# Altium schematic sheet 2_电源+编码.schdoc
size 431 x 309 mm; Symbol: Sheet-Symbol_A3; Device: Sheet-Symbol_A3; Company: 嘉立创EDA; Version: V1.0; Page Size: A3; @Project Name: 电容触摸键盘-第一验证板; @Page Count: 2; @Update Date: 2024-10-14; @Create Date: 2024-10-14; @Schematic Name: Schematic1; @Page No: 2; @Page Name: 电源+编码; Title Block Position: 3; Width: 1170; Height: 825; Region Start: 1; X Region Count: 6; Y Region Count: 4; Blade Width: 10; @Board Name: Board1; @Create Time: 23:12:04; @Update Time: 23:19:14
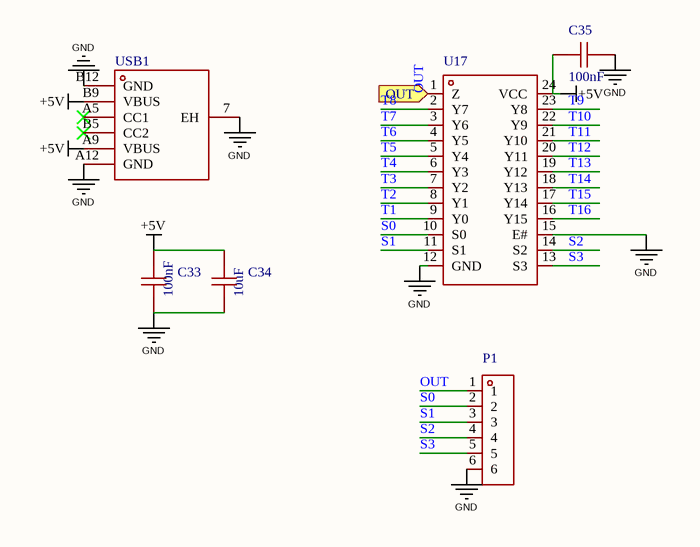
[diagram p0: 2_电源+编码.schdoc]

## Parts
C33  100nF  [C0603]
C34  10uF  [C0603]
C35  100nF  [C0603]
P1  2.54-1*6P母  [hdr-th_6p-p2.54-v-f]  (value not drawn)
U17  74HC4067PW/C2118  [TSSOP-24_L7.8-W4.4-P0.65-LS6.4-BL]  (value not drawn)
USB1  TYPE-C 6P  [TYPE-C-SMD_TYPE-C-6P]  (value not drawn)

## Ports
OUT (in)

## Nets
+5V: C33.1 C34.2 C35.1 U17.24(VCC) USB1.A9(VBUS) USB1.B9(VBUS)
GND: C33.2 C34.1 C35.2 P1.6 U17.12(GND) U17.15(E#) USB1.7(EH) USB1.A12(GND) USB1.B12(GND)
OUT: P1.1 U17.1(Z) ; port OUT
S0: P1.2 U17.10(S0)
S1: P1.3 U17.11(S1)
S2: P1.4 U17.14(S2)
S3: P1.5 U17.13(S3)
T1: U17.9(Y0)
T2: U17.8(Y1)
T3: U17.7(Y2)
T4: U17.6(Y3)
T5: U17.5(Y4)
T6: U17.4(Y5)
T7: U17.3(Y6)
T8: U17.2(Y7)
T9: U17.23(Y8)
T10: U17.22(Y9)
T11: U17.21(Y10)
T12: U17.20(Y11)
T13: U17.19(Y12)
T14: U17.18(Y13)
T15: U17.17(Y14)
T16: U17.16(Y15)

Not connected (* = marked no-connect by the designer): USB1 A5(CC1)* B5(CC2)*

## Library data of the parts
C33 C35 = CC0603KRX7R9BB104: 容值:100nF;精度:±10%;额定电压:50V;材质(温度系数):X7R;; Manufacturer: YAGEO(国巨); Add into BOM: yes; Tolerance: ±10%; Voltage Rated: 50V; Temperature Coefficient: X7R
C34 = CL10A106KP8NNNC: 容值:10uF;精度:±10%;额定电压:10V;材质(温度系数):X5R;; Manufacturer: SAMSUNG(三星); Add into BOM: yes; Tolerance: ±10%; Voltage Rated: 10V; Temperature Coefficient: X5R
P1 = 2.54-1*6P母: 插孔结构:1x6P;间距:2.54mm;行距:-;安装类型:直插;排数:单排;总孔位数:6P;塑高:-;触头材质:-;触头镀层:-;; Manufacturer: BOOMELE(博穆精密); Symbol: Header-Female-2.54_1x6; Add into BOM: yes; Holes Structure: 1x6P; Pitch: 2.54mm; Number of Holes: 6P
U17 = 74HC4067PW/C2118: Manufacturer: Nexperia(安世); Add into BOM: yes
USB1 = TYPE-C 6P: 连接器类型:Type-C;标准:USB 3.1;公母:母;安装方式:卧贴;触点数量:6P;端口数量:1;额定电流 - 电源:5A;工作温度范围:-40℃~+85℃;; Manufacturer: SHOU HAN(首韩); Add into BOM: yes; Gender: 母; Number of Ports: 1; Current Rating - Power (Max): 5A; Rated Voltage (Max): 20V; Connect-Disconnect Life: 3千次; Core Colour: 黑色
